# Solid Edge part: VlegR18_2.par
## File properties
Author: Türk
Template: Iso Part.par
Last saved by: Türk
Revision: 17
Application: Solid Edge
Accuracy: 0,990
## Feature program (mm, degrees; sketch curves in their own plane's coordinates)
pattern "PatternOccurrence_1"  XOffset = 45 deg
pattern "PatternOccurrence_2"  XCount = 5; XOffset = 72 deg
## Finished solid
Body 1: sheet body, 4 faces, 79 edges, 79 vertices.
  Faces by surface: plane 4
  Edges by curve: line 51, circle 18, spline 10
Body 2: solid body, 154 faces, 385 edges, 214 vertices, 2 internal voids.
  Faces by surface: cylinder 72, torus 31, plane 24, blend 14, cone 8, spun 5
  Edges by curve: circle 176, intersection 113, line 96
Bounding box of the edges (mm; curved faces can reach further): 200.000 x 457.200 x 457.200, from (-100, -228.6, -228.6) to (100, 228.6, 228.6).
Cylindrical faces by radius (mm): R4 x16, R6 x5, R15 x5, R25 x16, R80 x8, R150 x8, R174.2298 x8, R203.6 x2, R216.1 x2, R228.6 x2
Conical faces (half-angle, radius in mm at the cone's reference point): 2.0106 deg R178.4522 x2, 5.4632 deg R201.6202 x2, 54.824 deg R174.2298 x1, 54.824 deg R203.0605 x2, 54.824 deg R203.6 x1
Toroidal faces (ring radius, tube radius in mm): R79 r1 x7, R136.945 r40 x8, R170 r20 x8, R205.6 r2 x2, R214.1 r2 x2, R226.6 r2 x4
Planar faces by outward normal: +x 4, -x 4, oblique 16
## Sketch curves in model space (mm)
line (-30, -64.8293, 161.7195) -> (-30, -65.6784, 163.1901)
line (69.3, 0, 174.2298) -> (64.3, 0, 174.2298)
line (-30, 0, 62.5) -> (-35, 0, 62.5)
line (98, 0, 203.6) -> (18.9114, 0, 237.8791)
line (-98, 0, 203.6) -> (-98, 0, 288.5518)
line (-98, 0, 203.6) -> (-18.9114, 0, 237.8791)
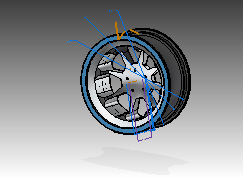
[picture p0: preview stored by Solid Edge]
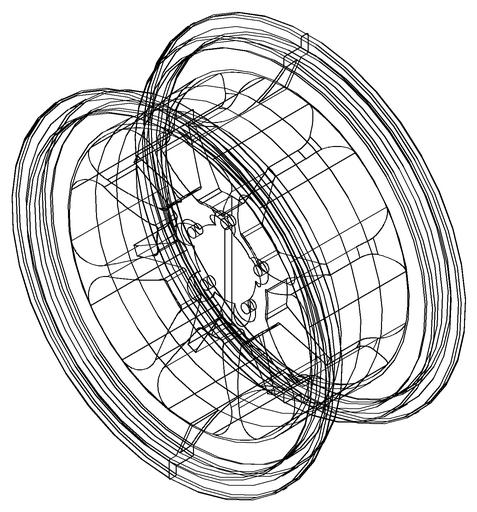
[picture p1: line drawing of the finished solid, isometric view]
